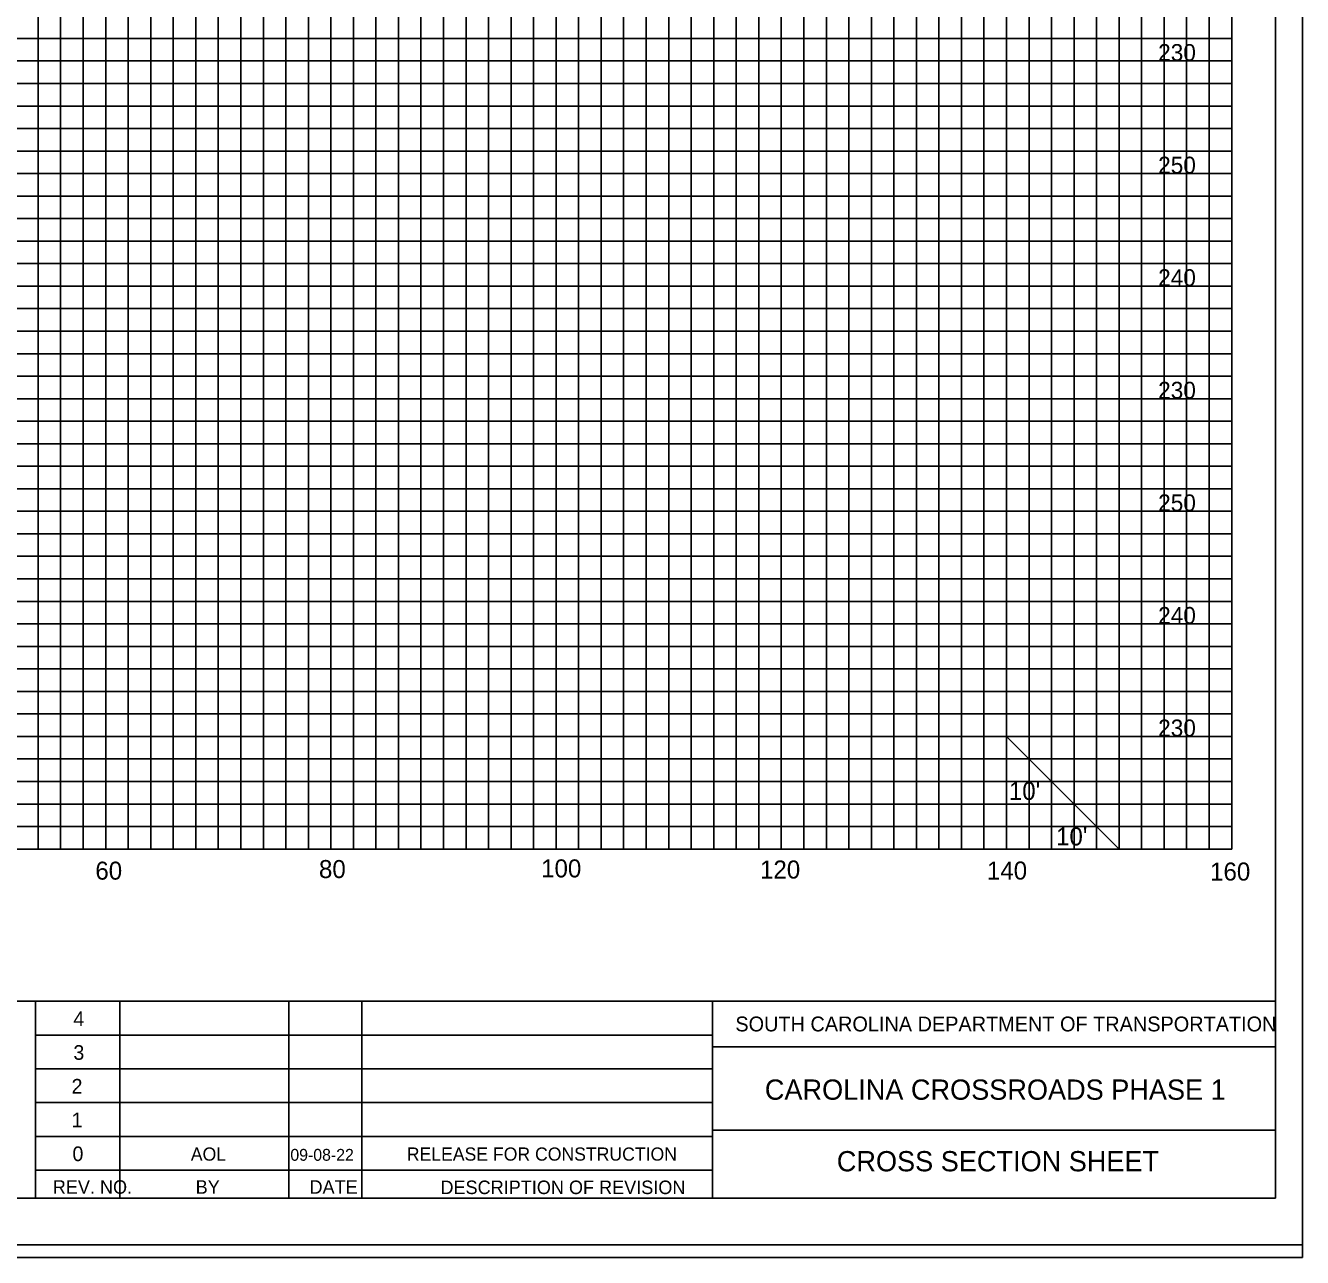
# Model space of a CAD drawing. Extents: x 967 to 1326, y 964 to 1744.
# Drawn here: x 1212.9 to 1326.3, y 963.7 to 1073.1 of the extents above; entities that cross this region are included whole.
import ezdxf

# ---------------------------------------------------------------- set-up
doc = ezdxf.new("R2010")
doc.units = 0
for name, color, linetype in [('Default', 7, 'Continuous'), ('RD_PD_PaveShd', 7, 'Continuous'), ('RD_XS_CurbBase', 7, 'Continuous'), ('RD_XS_TieSlope', 7, 'Continuous'), ('RD_XS_TX_Elev_PR', 7, 'Continuous'), ('RD_XS_TX_MkPT', 7, 'Continuous'), ('RD_XS_TX_Slope', 7, 'Continuous'), ('RD_XS_TX_TOC', 7, 'Continuous')]:
    doc.layers.add(name, color=color, linetype=linetype)

msp = doc.modelspace()

# ---------------------------------------------------------------- linework, layer by layer
at = {"layer": 'RD_PD_PaveShd'}
for p, q in [((1323.89, 1178.46), (1323.89, 968.98)), ((996.11, 986.49), (1323.89, 986.49)), ((1213.76, 968.94), (1213.76, 986.49)), ((1221.26, 968.95), (1221.26, 986.48)), ((1236.26, 968.95), (1236.26, 986.48)), ((1242.76, 968.95), (1242.76, 986.48)), ((1273.88, 968.98), (1273.88, 986.49)), ((1213.76, 983.48), (1273.88, 983.48)), ((1323.93, 982.43), (1273.88, 982.43)), ((1213.76, 980.48), (1273.88, 980.48)), ((1213.76, 977.48), (1273.88, 977.48)), ((1213.76, 974.48), (1273.88, 974.48)), ((1323.89, 975.04), (1273.88, 975.04)), ((1213.76, 971.48), (1273.88, 971.48)), ((1323.89, 968.98), (996.11, 968.98))]:
    msp.add_line(p, q, dxfattribs=at)
at = {"layer": 'RD_XS_CurbBase'}
msp.add_lwpolyline([(967.41, 963.72), (1326.28, 963.72), (1326.28, 1183.72), (967.41, 1183.72)], close=True, dxfattribs=at)
at = {"layer": 'RD_XS_TX_Elev_PR'}
for p, q in [((1220, 1000), (1220, 1170)), ((1230, 1000), (1230, 1170)), ((1240, 1000), (1240, 1170)), ((1250, 1000), (1250, 1170)), ((1260, 1000), (1260, 1170)), ((1270, 1000), (1270, 1170)), ((1280, 1000), (1280, 1170)), ((1290, 1000), (1290, 1170)), ((1300, 1000), (1300, 1170)), ((1310, 1000), (1310, 1170)), ((1320, 1000), (1320, 1170)), ((1000, 1070), (1320, 1070)), ((1000, 1060), (1320, 1060)), ((1000, 1050), (1320, 1050)), ((1000, 1040), (1320, 1040)), ((1000, 1030), (1320, 1030)), ((1000, 1020), (1320, 1020)), ((1000, 1010), (1320, 1010)), ((1000, 1000), (1320, 1000))]:
    msp.add_line(p, q, dxfattribs=at)
at = {"layer": 'RD_XS_TX_MkPT'}
msp.add_line((1300, 1010), (1310, 1000), dxfattribs=at)
at = {"layer": 'RD_XS_TX_Slope'}
for p, q in [((1214, 1000), (1214, 1170)), ((1216, 1000), (1216, 1170)), ((1218, 1000), (1218, 1170)), ((1222, 1000), (1222, 1170)), ((1224, 1000), (1224, 1170)), ((1226, 1000), (1226, 1170)), ((1228, 1000), (1228, 1170)), ((1232, 1000), (1232, 1170)), ((1234, 1000), (1234, 1170)), ((1236, 1000), (1236, 1170)), ((1238, 1000), (1238, 1170)), ((1242, 1000), (1242, 1170)), ((1244, 1000), (1244, 1170)), ((1246, 1000), (1246, 1170)), ((1248, 1000), (1248, 1170)), ((1252, 1000), (1252, 1170)), ((1254, 1000), (1254, 1170)), ((1256, 1000), (1256, 1170)), ((1258, 1000), (1258, 1170)), ((1262, 1000), (1262, 1170)), ((1264, 1000), (1264, 1170)), ((1266, 1000), (1266, 1170)), ((1268, 1000), (1268, 1170)), ((1272, 1000), (1272, 1170)), ((1274, 1000), (1274, 1170)), ((1276, 1000), (1276, 1170)), ((1278, 1000), (1278, 1170)), ((1282, 1000), (1282, 1170)), ((1284, 1000), (1284, 1170)), ((1286, 1000), (1286, 1170)), ((1288, 1000), (1288, 1170)), ((1292, 1000), (1292, 1170)), ((1294, 1000), (1294, 1170)), ((1296, 1000), (1296, 1170)), ((1298, 1000), (1298, 1170)), ((1302, 1000), (1302, 1170)), ((1304, 1000), (1304, 1170)), ((1306, 1000), (1306, 1170)), ((1308, 1000), (1308, 1170)), ((1312, 1000), (1312, 1170)), ((1314, 1000), (1314, 1170)), ((1316, 1000), (1316, 1170)), ((1318, 1000), (1318, 1170)), ((1000, 1072), (1320, 1072)), ((1000, 1068), (1320, 1068)), ((1000, 1066), (1320, 1066)), ((1000, 1064), (1320, 1064)), ((1000, 1062), (1320, 1062)), ((1000, 1058), (1320, 1058)), ((1000, 1056), (1320, 1056)), ((1000, 1054), (1320, 1054)), ((1000, 1052), (1320, 1052)), ((1000, 1048), (1320, 1048)), ((1000, 1046), (1320, 1046)), ((1000, 1044), (1320, 1044)), ((1000, 1042), (1320, 1042)), ((1000, 1038), (1320, 1038)), ((1000, 1036), (1320, 1036)), ((1000, 1034), (1320, 1034)), ((1000, 1032), (1320, 1032)), ((1000, 1028), (1320, 1028)), ((1000, 1026), (1320, 1026)), ((1000, 1024), (1320, 1024)), ((1000, 1022), (1320, 1022)), ((1000, 1018), (1320, 1018)), ((1000, 1016), (1320, 1016)), ((1000, 1014), (1320, 1014)), ((1000, 1012), (1320, 1012)), ((1000, 1008), (1320, 1008)), ((1000, 1006), (1320, 1006)), ((1000, 1004), (1320, 1004)), ((1000, 1002), (1320, 1002))]:
    msp.add_line(p, q, dxfattribs=at)
at = {"layer": 'RD_XS_TX_TOC'}
for points in [[(967.41, 963.72), (1326.28, 963.72), (1326.28, 1183.72), (967.41, 1183.72)], [(988.52, 964.84), (1326.28, 964.84), (1326.28, 1182.6), (988.52, 1182.6)]]:
    msp.add_lwpolyline(points, close=True, dxfattribs=at)

# ---------------------------------------------------------------- texts
at = {"layer": 'Default'}
for s, p in [('230', (1313.47, 1070)), ('250', (1313.47, 1060)), ('240', (1313.47, 1050)), ('230', (1313.47, 1040)), ('250', (1313.47, 1030)), ('240', (1313.47, 1020)), ('230', (1313.47, 1010))]:
    msp.add_text(s, height=1.5, dxfattribs=at).set_placement(p)
at = {"layer": 'RD_XS_TieSlope'}
for s, height, p in [('AOL', 1.17, (1227.56, 972.32)), ('09-08-22', 1.053, (1236.4, 972.31)), ('RELEASE FOR CONSTRUCTION', 1.17, (1246.74, 972.32))]:
    msp.add_text(s, height=height, dxfattribs=at).set_placement(p)
at = {"layer": 'RD_XS_TX_MkPT'}
for s, height, p in [("10'", 1.6, (1300.21, 1004.36)), ("10'", 1.6, (1304.4, 1000.32)), ('100', 1.6, (1258.67, 997.48)), ('60', 1.6, (1219.08, 997.28)), ('80', 1.6, (1238.94, 997.42)), ('120', 1.6, (1278.11, 997.38)), ('140', 1.6, (1298.26, 997.29)), ('160', 1.6, (1318.08, 997.2)), ('4', 1.3, (1217.13, 984.28)), ('SOUTH CAROLINA DEPARTMENT OF TRANSPORTATION', 1.32, (1275.92, 983.8)), ('3', 1.3, (1217.13, 981.28)), ('2', 1.3, (1216.97, 978.28)), ('1', 1.3, (1216.97, 975.28)), ('0', 1.3, (1217.05, 972.28)), ('REV. NO.', 1.2, (1215.3, 969.38)), ('BY', 1.2, (1227.99, 969.38)), ('DATE', 1.2, (1238.1, 969.38)), ('DESCRIPTION OF REVISION', 1.2, (1249.73, 969.35))]:
    msp.add_text(s, height=height, dxfattribs=at).set_placement(p)
for s, p in [('CAROLINA CROSSROADS PHASE 1', (1278.54, 977.73)), ('CROSS SECTION SHEET', (1284.93, 971.37))]:
    msp.add_text(s, height=1.8, rotation=0, dxfattribs=at).set_placement(p)

doc.saveas('drawing.dxf')
